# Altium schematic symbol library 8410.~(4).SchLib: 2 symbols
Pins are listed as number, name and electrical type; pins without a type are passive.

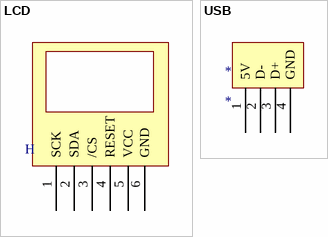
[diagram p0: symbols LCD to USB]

## LCD
designator H  (value not drawn)
pins: 1 SCK, 2 SDA, 3 /CS, 4 RESET, 5 VCC, 6 GND

## USB
designator *
pins: 1 5V, 2 D-, 3 D+, 4 GND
